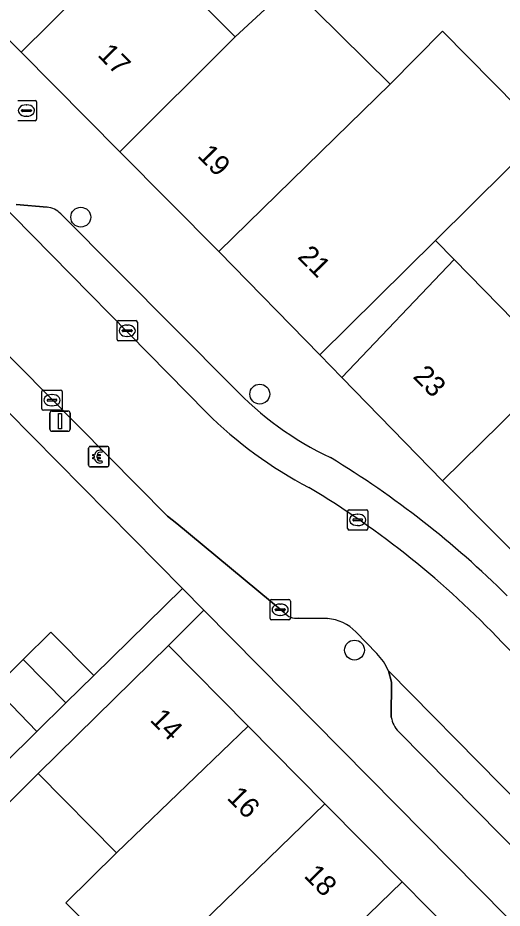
# Model space of a CAD drawing. Extents: x 160102 to 160934, y 382045 to 382923.
# Drawn here: x 160653.65 to 160677.52, y 382620.95 to 382664.84 of the extents above; entities that cross this region are included whole.
import ezdxf

# ---------------------------------------------------------------- set-up
doc = ezdxf.new("R2010")
doc.units = 0
for name, color, linetype in [('IMGEO_Betaalautomaat', 7, 'Continuous'), ('IMGEO_Boom', 7, 'Continuous'), ('IMGEO_Brandkraan', 7, 'Continuous'), ('IMGEO_Erf', 7, 'Continuous'), ('IMGEO_Kolk', 7, 'Continuous'), ('IMGEO_Lichtmast', 7, 'Continuous'), ('IMGEO_Pand', 7, 'Continuous'), ('IMGEO_Pand_nummerreeks', 7, 'Continuous'), ('IMGEO_Pand_overbouw', 7, 'Continuous'), ('IMGEO_Parkeervlak_open', 7, 'Continuous'), ('IMGEO_Rijbaan_lokaal_open', 7, 'Continuous'), ('IMGEO_Voetpad_open', 7, 'Continuous')]:
    doc.layers.add(name, color=color, linetype=linetype)

msp = doc.modelspace()

# ---------------------------------------------------------------- linework, layer by layer
at = {"layer": 'IMGEO_Betaalautomaat'}
for p, q in [((160657.145, 382642.781), (160657.145, 382643.622)), ((160657.145, 382643.622), (160657.145, 382642.781)), ((160657.22, 382643.705), (160658.061, 382643.705)), ((160658.061, 382643.705), (160657.22, 382643.705)), ((160658.144, 382643.631), (160658.144, 382642.79)), ((160658.144, 382642.79), (160658.144, 382643.631)), ((160657.428, 382643.169), (160657.428, 382643.237)), ((160657.549, 382643.237), (160657.549, 382643.169)), ((160657.807, 382643.51), (160657.79, 382643.41)), ((160657.794, 382643.004), (160657.816, 382642.917)), ((160658.07, 382642.706), (160657.229, 382642.706)), ((160657.229, 382642.706), (160658.07, 382642.706))]:
    msp.add_line(p, q, dxfattribs=at)
for points in [[(160657.428, 382643.237), (160657.359, 382643.237), (160657.359, 382643.306), (160657.438, 382643.306)], [(160657.433, 382643.1), (160657.359, 382643.1), (160657.359, 382643.169), (160657.428, 382643.169)], [(160657.56, 382643.306), (160657.707, 382643.306), (160657.707, 382643.237), (160657.549, 382643.237)], [(160657.549, 382643.169), (160657.707, 382643.169), (160657.707, 382643.1), (160657.563, 382643.1)]]:
    msp.add_lwpolyline(points, dxfattribs=at)
for centre, radius, start, end in [((160657.223, 382643.628), 0.0779, 92.4484, 184.2845), ((160657.223, 382643.628), 0.0779, 92.4484, 184.2845), ((160658.067, 382643.628), 0.0779, 2.4484, 94.2845), ((160658.067, 382643.628), 0.0779, 2.4484, 94.2845), ((160657.721, 382643.23), 0.293, 73.014, 165.0139), ((160657.727, 382643.243), 0.179, 69.3236, 159.5683), ((160657.223, 382642.784), 0.0779, 182.4484, 274.2845), ((160657.223, 382642.784), 0.0779, 182.4484, 274.2845), ((160657.694, 382643.155), 0.267, 191.8096, 297.0389), ((160657.727, 382643.17), 0.179, 202.7625, 291.8693), ((160658.067, 382642.784), 0.0779, 272.4484, 4.2845), ((160658.067, 382642.784), 0.0779, 272.4484, 4.2845)]:
    msp.add_arc(centre, radius, start, end, dxfattribs=at)
at = {"layer": 'IMGEO_Boom'}
for centre in [(160656.758, 382655.009), (160665.578, 382646.287), (160670.245, 382633.668)]:
    msp.add_circle(centre, 0.489, dxfattribs=at)
at = {"layer": 'IMGEO_Brandkraan'}
for p, q in [((160653.655, 382660.765), (160654.507, 382660.765)), ((160653.839, 382660.259), (160653.839, 382660.271)), ((160653.882, 382660.308), (160654.28, 382660.308)), ((160654.068, 382660.545), (160654.093, 382660.545)), ((160654.323, 382660.271), (160654.323, 382660.259)), ((160654.581, 382660.691), (160654.581, 382659.839)), ((160654.277, 382660.222), (160653.879, 382660.222)), ((160654.091, 382659.985), (160654.066, 382659.985)), ((160654.507, 382659.765), (160653.655, 382659.765))]:
    msp.add_line(p, q, dxfattribs=at)
for points in [[(160653.655, 382660.765), (160654.507, 382660.765)], [(160654.581, 382660.691), (160654.581, 382659.839)], [(160654.507, 382659.765), (160653.655, 382659.765)]]:
    msp.add_lwpolyline(points, dxfattribs=at)
for centre, radius, start, end in [((160654.505, 382660.689), 0.0765, 1.552, 88.448), ((160654.505, 382660.689), 0.0765, 1.552, 88.448), ((160653.879, 382660.268), 0.0403, 85.8775, 175.7526), ((160654.284, 382660.27), 0.0386, 1.7309, 96.639), ((160653.876, 382660.258), 0.0366, 178.938, 274.7102), ((160654.28, 382660.265), 0.043, 264.8664, 352.4533), ((160654.505, 382659.841), 0.0765, 271.552, 358.448), ((160654.505, 382659.841), 0.0765, 271.552, 358.448)]:
    msp.add_arc(centre, radius, start, end, dxfattribs=at)
for centre, major_axis, ratio, start_param, end_param in [((160654.067, 382660.265), (-0.387, 0.002), 0.722429, 4.712389, 7.853982), ((160654.092, 382660.265), (-0.39, 0.002), 0.717154, 1.570796, 4.712389)]:
    msp.add_ellipse(centre, major_axis=major_axis, ratio=ratio, start_param=start_param, end_param=end_param, dxfattribs=at)
at = {"layer": 'IMGEO_Erf'}
for points in [[(160661.615, 382666.677), (160664.371, 382663.893), (160667.096, 382666.434), (160672.007, 382661.561), (160674.579, 382664.179), (160679.567, 382659.14), (160674.237, 382653.864), (160668.534, 382648.218), (160669.618, 382647.108), (160675.152, 382652.928), (160680.312, 382647.65)], [(160649.709, 382624.834), (160654.597, 382629.659), (160652.498, 382631.802), (160653.912, 382633.199), (160655.28, 382634.551), (160657.395, 382632.411), (160661.762, 382636.708), (160646.97, 382651.686)], [(160712.982, 382584.842), (160662.826, 382635.631), (160661.073, 382633.9), (160665.003, 382629.92), (160668.783, 382626.093), (160672.588, 382622.239), (160676.381, 382618.398)], [(160657.989, 382619.218), (160656.021, 382621.212), (160658.522, 382623.682), (160654.663, 382627.589), (160645.692, 382618.673)]]:
    msp.add_lwpolyline(points, dxfattribs=at)
at = {"layer": 'IMGEO_Kolk'}
for p, q in [((160658.545, 382648.983), (160658.545, 382649.835)), ((160658.62, 382649.909), (160659.472, 382649.909)), ((160659.546, 382649.835), (160659.546, 382648.983)), ((160658.804, 382649.403), (160658.804, 382649.415)), ((160659.242, 382649.366), (160658.844, 382649.366)), ((160658.847, 382649.452), (160659.245, 382649.452)), ((160659.033, 382649.689), (160659.058, 382649.689)), ((160659.288, 382649.415), (160659.288, 382649.403)), ((160659.472, 382648.909), (160658.62, 382648.909)), ((160659.056, 382649.129), (160659.031, 382649.129)), ((160654.839, 382645.562), (160654.839, 382646.414)), ((160654.914, 382646.488), (160655.766, 382646.488)), ((160655.327, 382646.268), (160655.352, 382646.268)), ((160655.84, 382646.414), (160655.84, 382645.562)), ((160655.098, 382645.982), (160655.098, 382645.994)), ((160655.536, 382645.945), (160655.138, 382645.945)), ((160655.141, 382646.031), (160655.539, 382646.031)), ((160655.582, 382645.994), (160655.582, 382645.982)), ((160655.766, 382645.488), (160654.914, 382645.488)), ((160655.35, 382645.708), (160655.325, 382645.708)), ((160669.978, 382640.588), (160670.83, 382640.588)), ((160669.903, 382639.662), (160669.903, 382640.514)), ((160670.162, 382640.082), (160670.162, 382640.094)), ((160670.205, 382640.131), (160670.603, 382640.131)), ((160670.391, 382640.368), (160670.416, 382640.368)), ((160670.646, 382640.094), (160670.646, 382640.082)), ((160670.904, 382640.514), (160670.904, 382639.662)), ((160670.6, 382640.045), (160670.202, 382640.045)), ((160670.414, 382639.808), (160670.389, 382639.808)), ((160670.83, 382639.588), (160669.978, 382639.588)), ((160666.158, 382636.16), (160667.01, 382636.16)), ((160666.083, 382635.234), (160666.083, 382636.086)), ((160666.385, 382635.703), (160666.783, 382635.703)), ((160666.571, 382635.94), (160666.596, 382635.94)), ((160667.084, 382636.086), (160667.084, 382635.234)), ((160666.342, 382635.654), (160666.342, 382635.666)), ((160666.78, 382635.617), (160666.382, 382635.617)), ((160666.594, 382635.38), (160666.569, 382635.38)), ((160666.826, 382635.666), (160666.826, 382635.654)), ((160667.01, 382635.16), (160666.158, 382635.16))]:
    msp.add_line(p, q, dxfattribs=at)
for points in [[(160658.545, 382648.983), (160658.545, 382649.835)], [(160658.62, 382649.909), (160659.472, 382649.909)], [(160659.546, 382649.835), (160659.546, 382648.983)], [(160659.472, 382648.909), (160658.62, 382648.909)], [(160654.839, 382645.562), (160654.839, 382646.414)], [(160654.914, 382646.488), (160655.766, 382646.488)], [(160655.84, 382646.414), (160655.84, 382645.562)], [(160655.766, 382645.488), (160654.914, 382645.488)], [(160669.978, 382640.588), (160670.83, 382640.588)], [(160669.903, 382639.662), (160669.903, 382640.514)], [(160670.904, 382640.514), (160670.904, 382639.662)], [(160670.83, 382639.588), (160669.978, 382639.588)], [(160666.158, 382636.16), (160667.01, 382636.16)], [(160666.083, 382635.234), (160666.083, 382636.086)], [(160667.084, 382636.086), (160667.084, 382635.234)], [(160667.01, 382635.16), (160666.158, 382635.16)]]:
    msp.add_lwpolyline(points, dxfattribs=at)
for centre, radius, start, end in [((160658.622, 382649.833), 0.0765, 91.552, 178.448), ((160658.622, 382649.833), 0.0765, 91.552, 178.448), ((160659.47, 382649.833), 0.0765, 1.552, 88.448), ((160659.47, 382649.833), 0.0765, 1.552, 88.448), ((160658.844, 382649.412), 0.0403, 85.8775, 175.7526), ((160658.841, 382649.402), 0.0366, 178.938, 274.7102), ((160659.245, 382649.409), 0.043, 264.8664, 352.4533), ((160659.249, 382649.414), 0.0386, 1.7309, 96.639), ((160658.622, 382648.985), 0.0765, 181.552, 268.448), ((160658.622, 382648.985), 0.0765, 181.552, 268.448), ((160659.47, 382648.985), 0.0765, 271.552, 358.448), ((160659.47, 382648.985), 0.0765, 271.552, 358.448), ((160654.916, 382646.412), 0.0765, 91.552, 178.448), ((160654.916, 382646.412), 0.0765, 91.552, 178.448), ((160655.764, 382646.412), 0.0765, 1.552, 88.448), ((160655.764, 382646.412), 0.0765, 1.552, 88.448), ((160655.138, 382645.991), 0.0403, 85.8775, 175.7526), ((160655.135, 382645.981), 0.0366, 178.938, 274.7102), ((160655.539, 382645.988), 0.043, 264.8664, 352.4533), ((160655.543, 382645.993), 0.0386, 1.7309, 96.639), ((160654.916, 382645.564), 0.0765, 181.552, 268.448), ((160654.916, 382645.564), 0.0765, 181.552, 268.448), ((160655.764, 382645.564), 0.0765, 271.552, 358.448), ((160655.764, 382645.564), 0.0765, 271.552, 358.448), ((160669.98, 382640.512), 0.0765, 91.552, 178.448), ((160669.98, 382640.512), 0.0765, 91.552, 178.448), ((160670.828, 382640.512), 0.0765, 1.552, 88.448), ((160670.828, 382640.512), 0.0765, 1.552, 88.448), ((160670.202, 382640.091), 0.0403, 85.8775, 175.7526), ((160670.199, 382640.081), 0.0366, 178.938, 274.7102), ((160670.603, 382640.088), 0.043, 264.8664, 352.4533), ((160670.607, 382640.093), 0.0386, 1.7309, 96.639), ((160669.98, 382639.664), 0.0765, 181.552, 268.448), ((160669.98, 382639.664), 0.0765, 181.552, 268.448), ((160670.828, 382639.664), 0.0765, 271.552, 358.448), ((160670.828, 382639.664), 0.0765, 271.552, 358.448), ((160666.16, 382636.084), 0.0765, 91.552, 178.448), ((160666.16, 382636.084), 0.0765, 91.552, 178.448), ((160667.008, 382636.084), 0.0765, 1.552, 88.448), ((160667.008, 382636.084), 0.0765, 1.552, 88.448), ((160666.382, 382635.663), 0.0403, 85.8775, 175.7526), ((160666.787, 382635.665), 0.0386, 1.7309, 96.639), ((160666.379, 382635.653), 0.0366, 178.938, 274.7102), ((160666.783, 382635.66), 0.043, 264.8664, 352.4533), ((160666.16, 382635.236), 0.0765, 181.552, 268.448), ((160666.16, 382635.236), 0.0765, 181.552, 268.448), ((160667.008, 382635.236), 0.0765, 271.552, 358.448), ((160667.008, 382635.236), 0.0765, 271.552, 358.448)]:
    msp.add_arc(centre, radius, start, end, dxfattribs=at)
for centre, major_axis, ratio, start_param, end_param in [((160659.032, 382649.409), (-0.387, 0.002), 0.722429, 4.712389, 7.853982), ((160659.057, 382649.409), (-0.39, 0.002), 0.717154, 1.570796, 4.712389), ((160655.326, 382645.988), (-0.387, 0.002), 0.722429, 4.712389, 7.853982), ((160655.351, 382645.988), (-0.39, 0.002), 0.717154, 1.570796, 4.712389), ((160670.39, 382640.088), (-0.387, 0.002), 0.722429, 4.712389, 7.853982), ((160670.415, 382640.088), (-0.39, 0.002), 0.717154, 1.570796, 4.712389), ((160666.57, 382635.66), (-0.387, 0.002), 0.722429, 4.712389, 7.853982), ((160666.595, 382635.66), (-0.39, 0.002), 0.717154, 1.570796, 4.712389)]:
    msp.add_ellipse(centre, major_axis=major_axis, ratio=ratio, start_param=start_param, end_param=end_param, dxfattribs=at)
at = {"layer": 'IMGEO_Lichtmast'}
for p, q in [((160655.237, 382644.554), (160655.237, 382645.354)), ((160655.237, 382645.354), (160655.237, 382644.554)), ((160655.337, 382645.454), (160656.127, 382645.454)), ((160656.127, 382645.454), (160655.337, 382645.454)), ((160656.227, 382645.354), (160656.227, 382644.554)), ((160656.227, 382644.554), (160656.227, 382645.354)), ((160656.127, 382644.454), (160655.337, 382644.454)), ((160655.337, 382644.454), (160656.127, 382644.454))]:
    msp.add_line(p, q, dxfattribs=at)
msp.add_lwpolyline([(160655.657, 382645.329), (160655.807, 382645.329), (160655.807, 382644.579), (160655.657, 382644.579), (160655.657, 382645.329)], dxfattribs=at)
for centre, start, end in [((160655.337, 382645.354), 90, 180), ((160655.337, 382645.354), 90, 180), ((160656.127, 382645.354), 0, 90), ((160656.127, 382645.354), 360, 90), ((160655.337, 382644.554), 180, 270), ((160655.337, 382644.554), 180, 270), ((160656.127, 382644.554), 270, 0), ((160656.127, 382644.554), 270, 0)]:
    msp.add_arc(centre, 0.1, start, end, dxfattribs=at)
at = {"layer": 'IMGEO_Pand'}
for points in [[(160653.827, 382663.146), (160659.514, 382668.799), (160654.582, 382673.781), (160652.437, 382671.657), (160648.883, 382668.139)], [(160664.371, 382663.893), (160661.615, 382666.677), (160659.514, 382668.799), (160653.827, 382663.146), (160658.688, 382658.236)], [(160669.299, 382658.916), (160672.007, 382661.561), (160667.096, 382666.434), (160664.371, 382663.893), (160658.688, 382658.236), (160663.563, 382653.311)], [(160674.237, 382653.864), (160679.567, 382659.14), (160674.579, 382664.179), (160672.007, 382661.561), (160669.299, 382658.916), (160663.563, 382653.311), (160668.534, 382648.218)], [(160680.312, 382647.65), (160675.152, 382652.928), (160669.618, 382647.108), (160674.589, 382642.015)], [(160680.312, 382647.65), (160674.589, 382642.015), (160679.49, 382637.064), (160685.179, 382642.734)], [(160653.912, 382633.199), (160656.029, 382631.067), (160657.395, 382632.411), (160655.28, 382634.551)], [(160665.003, 382629.92), (160661.073, 382633.9), (160657.511, 382630.393), (160654.663, 382627.589), (160658.522, 382623.682)], [(160653.912, 382633.199), (160652.498, 382631.802), (160654.597, 382629.659), (160656.029, 382631.067)], [(160668.783, 382626.093), (160665.003, 382629.92), (160658.522, 382623.682), (160656.021, 382621.212), (160657.989, 382619.218), (160656.583, 382617.83), (160658.41, 382615.979), (160660.539, 382618.082)], [(160664.339, 382614.233), (160672.588, 382622.239), (160668.783, 382626.093), (160660.539, 382618.082)], [(160676.381, 382618.398), (160672.588, 382622.239), (160664.339, 382614.233), (160663.739, 382613.639), (160667.54, 382609.79), (160669.919, 382612.139)]]:
    msp.add_lwpolyline(points, close=True, dxfattribs=at)
at = {"layer": 'IMGEO_Pand_overbouw'}
msp.add_lwpolyline([(160675.152, 382652.928), (160674.237, 382653.864), (160668.534, 382648.218), (160669.618, 382647.108)], close=True, dxfattribs=at)
at = {"layer": 'IMGEO_Parkeervlak_open'}
for points in [[(160652.444, 382656.062), (160662.945, 382645.377)], [(160655.096, 382655.497), (160653.571, 382655.632)], [(160664.249, 382646.651), (160655.77, 382655.181)], [(160709.547, 382594.453), (160692.265, 382611.995), (160688.533, 382615.784), (160671.916, 382632.651), (160672.065, 382632.08), (160672.059, 382630.363)], [(160672.412, 382629.652), (160688.913, 382612.948), (160689.943, 382613.949), (160690.574, 382613.342), (160689.516, 382612.338), (160706.263, 382595.385)]]:
    msp.add_lwpolyline(points, dxfattribs=at)
for centre, radius, start, end in [((160655.003, 382654.422), 1.079, 44.7069, 85.0548), ((160676.044, 382657.828), 16.25, 223.4598, 244.5534), ((160678.099, 382660.798), 21.62, 225.5005, 242.1541), ((160644.698, 382603.008), 46.962, 45.2318, 58.7473), ((160645.108, 382603.375), 44.625, 43.4149, 59.1365), ((160673.39, 382630.581), 1.349, 189.2947, 223.5126)]:
    msp.add_arc(centre, radius, start, end, dxfattribs=at)
at = {"layer": 'IMGEO_Rijbaan_lokaal_open'}
for points in [[(160662.945, 382645.377), (160652.444, 382656.062), (160652.209, 382656.301), (160649.899, 382654.041)], [(160650.759, 382650.645), (160661.023, 382640.273), (160661.496, 382639.903), (160666.785, 382635.514)], [(160667.492, 382635.249), (160668.917, 382635.219)], [(160670.313, 382634.568), (160671.343, 382633.499)], [(160671.916, 382632.651), (160688.533, 382615.784), (160692.094, 382619.309), (160677.523, 382634.045)]]:
    msp.add_lwpolyline(points, dxfattribs=at)
for centre, radius, start, end in [((160678.099, 382660.798), 21.62, 225.5005, 242.1541), ((160645.108, 382603.375), 44.625, 43.4149, 59.1365), ((160667.383, 382636.035), 0.793, 221.042, 277.8636), ((160668.761, 382633.062), 2.162, 44.1318, 85.8659), ((160669.483, 382631.625), 2.64, 22.8721, 45.2223)]:
    msp.add_arc(centre, radius, start, end, dxfattribs=at)
at = {"layer": 'IMGEO_Voetpad_open'}
for points in [[(160700.619, 382615.839), (160689.9, 382626.667), (160690.212, 382626.976), (160688.279, 382628.929), (160687.908, 382628.562), (160684.405, 382632.1), (160679.49, 382637.064), (160674.589, 382642.015), (160669.618, 382647.108), (160668.534, 382648.218), (160663.563, 382653.311), (160658.688, 382658.236), (160653.827, 382663.146), (160648.883, 382668.139)], [(160646.03, 382655.434), (160645.257, 382656.136), (160645.09, 382655.921), (160643.916, 382654.779), (160646.97, 382651.686), (160661.762, 382636.708), (160662.826, 382635.631), (160712.982, 382584.842), (160713.731, 382584.084), (160713.103, 382583.387), (160713.694, 382582.756), (160716.749, 382579.675), (160720.025, 382576.37), (160723.85, 382572.511), (160727.058, 382569.275), (160727.75, 382568.555), (160729.974, 382567.003), (160733.36, 382564.639), (160738.891, 382560.779), (160747.475, 382554.898), (160750.073, 382558.043), (160747.665, 382559.678), (160746.901, 382560.196)], [(160653.571, 382655.632), (160655.096, 382655.497)], [(160655.77, 382655.181), (160664.249, 382646.651)], [(160666.785, 382635.514), (160661.496, 382639.903), (160661.023, 382640.273), (160650.759, 382650.645)], [(160645.692, 382618.673), (160654.663, 382627.589), (160657.511, 382630.393), (160661.073, 382633.9), (160662.826, 382635.631), (160661.762, 382636.708), (160657.395, 382632.411), (160656.029, 382631.067), (160654.597, 382629.659), (160649.709, 382624.834)], [(160668.917, 382635.219), (160667.492, 382635.249)], [(160671.343, 382633.499), (160670.313, 382634.568)], [(160672.059, 382630.363), (160672.065, 382632.08), (160671.916, 382632.651)], [(160689.516, 382612.338), (160690.574, 382613.342), (160689.943, 382613.949), (160688.913, 382612.948), (160672.412, 382629.652)]]:
    msp.add_lwpolyline(points, dxfattribs=at)
for centre, radius, start, end in [((160655.003, 382654.422), 1.079, 44.7069, 85.0548), ((160676.044, 382657.828), 16.25, 223.4598, 244.5534), ((160644.698, 382603.008), 46.962, 45.2318, 58.7473), ((160667.383, 382636.035), 0.793, 221.042, 277.8636), ((160668.761, 382633.062), 2.162, 44.1318, 85.8659), ((160669.483, 382631.625), 2.64, 22.8721, 45.2223), ((160673.39, 382630.581), 1.349, 189.2947, 223.5126)]:
    msp.add_arc(centre, radius, start, end, dxfattribs=at)

# ---------------------------------------------------------------- texts
at = {"layer": 'IMGEO_Pand_nummerreeks'}
for s, rotation, p in [('17', 314.7134, (160657.538, 382662.976)), ('19', 314.7133, (160662.461, 382658.006)), ('21', 314.7133, (160667.398, 382653.02)), ('23', 314.7138, (160673.083, 382647.118)), ('14', 314.6388, (160660.12, 382630.197)), ('16', 314.6388, (160663.914, 382626.355)), ('18', 314.6388, (160667.71, 382622.511))]:
    msp.add_text(s, height=1, rotation=rotation, dxfattribs=at).set_placement(p)

doc.saveas('drawing.dxf')
